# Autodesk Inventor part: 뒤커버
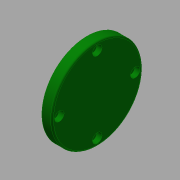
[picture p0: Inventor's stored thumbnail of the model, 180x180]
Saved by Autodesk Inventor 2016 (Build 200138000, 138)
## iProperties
Created: 2015-09
Part Number: 뒤커버
Material: 알루미늄 6061
Document SubType Name: Modeling
Designer: mduedu
Density: 2.71 g/cm^3
Mass: 54.0417 g
Surface Area: 84.9688 cm^2
Volume: 19.9416 cm^3
Appearance: 진녹색
Author: mduedu
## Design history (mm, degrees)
sketch "스케치1"
  geometry: L1 (-15.5, 47)-(-15.5, 78); L2 (-15.5, 78)-(-22.5, 78); L3 (-22.5, 78)-(-22.5, 67); L4 (-25.5, 67)-(-25.5, 47); L5 (-79.5, 39.5)-(-79.5, 54.5) reference; L6 (48.5, 54.5)-(48.5, 39.5) reference; L7 (-79.5, 47)-(48.5, 47); L8 (-22.5, 67)-(-25.5, 67); L9 (-25.5, 47)-(-15.5, 47); 1 further point
  constraints: 14 end point, 4 midpoint, 3 parallel, 1 collinear, 1 point on line, 1 vertical
  dimensions: "d6" = 62 diameter of L2 L7; "d7" = 7 distance of L1.end L2.end; "d8" = 40 diameter of L3.end L7; "d32" = 10 distance between parallel lines of L1 L4
revolve "회전1" sketch "스케치1" stored, may be unused: angle "d4" = 90 deg
sketch "스케치4"
  geometry: C1 r 31 at (0, 0) reference; 2 further points
  constraints: 1 coincident
hole "구멍3" sketch "스케치4" at (0, 0) diameter "d33" = 33; stored, may be unused: countersink angle "d37" = 90 deg, drill point angle "d39" = 0 deg; dims "d34" = 6, "d35" = 4, "d36" = 2, "d38" = 5
fillet "모깎기4" dims "d40" = 1
chamfer "모따기2" distance "d41" = 1; stored, may be unused: second distance "d42" = 2, angle "d43" = 45 deg
sketch "스케치6" dims "d56" = 52
  geometry: C1 r 31 at (0, 0) reference; 5 further points
  constraints: 2 vertical alignment, 1 coincident, 7 other
  dimensions: "d59" = 360 deg dimension on C1.centre point (0, 26) (derived)
hole "구멍4" sketch "스케치6" at (0, 26), (-26, 0), (0, -26), (26, 0) diameter "d49" = 3.4; stored, may be unused: countersink angle "d53" = 90 deg, drill point angle "d55" = 0 deg; dims "d50" = 6, "d51" = 6.5, "d52" = 3.4, "d54" = 8
node "솔리드1"
node "참조1"
node "참조2"
